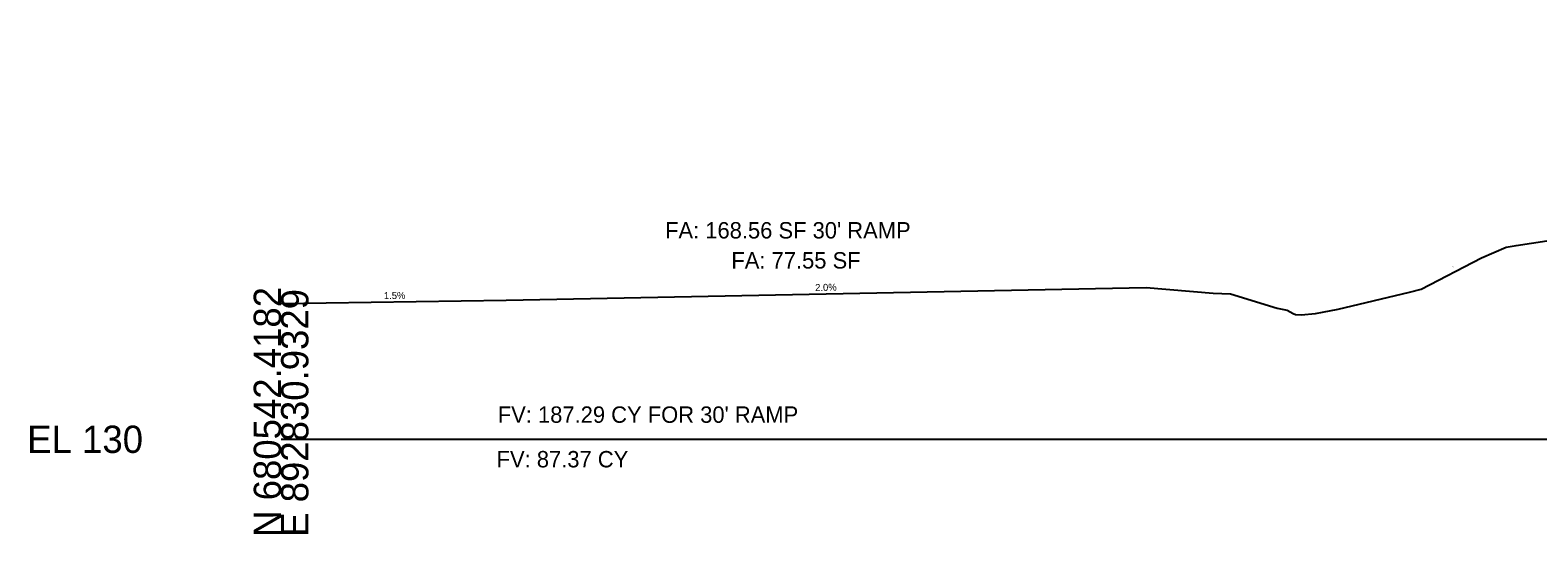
# Model space of a CAD drawing. Extents: x -26 to 4303, y -13 to 10775.
# Drawn here: x -25.7 to 128.7, y 2490.3 to 2541.9 of the extents above; entities that cross this region are included whole.
import ezdxf

# ---------------------------------------------------------------- set-up
doc = ezdxf.new("R2010")
doc.units = 0
for name, color, linetype in [('_CIVIL_CONSTRUCTION', 7, 'Continuous'), ('CONST_DCH', 7, 'Continuous'), ('Draft_XS_Grid', 7, 'Continuous'), ('DTM_CORRIDOR', 7, 'Continuous'), ('DTM_TEMP_DROP', 7, 'Continuous'), ('DTM_X_GROUND', 7, 'Continuous'), ('SLOPE_STAKES_FILL', 7, 'Continuous'), ('XS_CELL', 7, 'Continuous'), ('XS_M_SHAPES_EARTHWORK', 7, 'Continuous'), ('XS_P_TX_FS_BS', 7, 'Continuous'), ('XS_SHEET_EW_TX_VOLUME', 7, 'Continuous')]:
    doc.layers.add(name, color=color, linetype=linetype)

msp = doc.modelspace()

# ---------------------------------------------------------------- linework, layer by layer
at = {"layer": 'DTM_X_GROUND'}
msp.add_lwpolyline([(0, 2513.91), (23.05, 2514.25), (88.57, 2515.57), (95.44, 2514.99), (97.22, 2514.9), (101.99, 2513.45), (103.01, 2513.23), (103.64, 2512.88), (103.87, 2512.79), (104.47, 2512.77), (105.92, 2512.89), (106.65, 2513.04), (108.25, 2513.33), (115.54, 2515.07), (116.76, 2515.39), (122.93, 2518.6), (125.45, 2519.68), (126.48, 2519.85), (129.62, 2520.34)], dxfattribs=at)
at = {"layer": 'XS_CELL'}
msp.add_line((0, 2500), (150, 2500), dxfattribs=at)

# ---------------------------------------------------------------- texts
at = {"layer": '_CIVIL_CONSTRUCTION'}
for p in [(125.5, 2541.85), (127.5, 2541.93), (125.51, 2541.16)]:
    msp.add_text('X', height=0.001, dxfattribs=at).set_placement(p)
at = {"layer": 'CONST_DCH'}
msp.add_text('X', height=0.12, dxfattribs=at).set_placement((105.41, 2512.79))
at = {"layer": 'Draft_XS_Grid'}
msp.add_text('-', height=0.0001, dxfattribs=at).set_placement((0, 2500))
at = {"layer": 'DTM_CORRIDOR'}
msp.add_text('X', height=0.12, dxfattribs=at).set_placement((105.41, 2512.79))
at = {"layer": 'DTM_TEMP_DROP'}
msp.add_text('X', height=0.001, dxfattribs=at).set_placement((123.5, 2541.77))
at = {"layer": 'SLOPE_STAKES_FILL'}
msp.add_text('X', height=0.12, dxfattribs=at).set_placement((119.96, 2517.64))
at = {"layer": 'XS_CELL'}
for s, p in [('N 680542.4182', (0, 2490)), ('E 892830.9329', (2.8, 2490))]:
    msp.add_text(s, height=2.8, rotation=90, dxfattribs=at).set_placement(p)
msp.add_text('EL 130', height=2.8, dxfattribs=at).set_placement((-26, 2498.6))
at = {"layer": 'XS_M_SHAPES_EARTHWORK'}
for s, p in [("FV: 187.29 CY FOR 30' RAMP", (22.19, 2501.69)), ('FV: 87.37 CY', (22.07, 2497.12))]:
    msp.add_text(s, height=1.68, dxfattribs=at).set_placement(p)
at = {"layer": 'XS_P_TX_FS_BS'}
for s, rotation, p in [('1.5%', 0.8566, (10.54, 2514.36)), ('2.0%', 1.1513, (54.7, 2515.19))]:
    msp.add_text(s, height=0.72, rotation=rotation, dxfattribs=at).set_placement(p)
at = {"layer": 'XS_SHEET_EW_TX_VOLUME'}
for s, p in [("FA: 168.56 SF 30' RAMP", (39.32, 2520.58)), ('FA: 77.55 SF', (46.11, 2517.5))]:
    msp.add_text(s, height=1.68, dxfattribs=at).set_placement(p)

doc.saveas('drawing.dxf')
